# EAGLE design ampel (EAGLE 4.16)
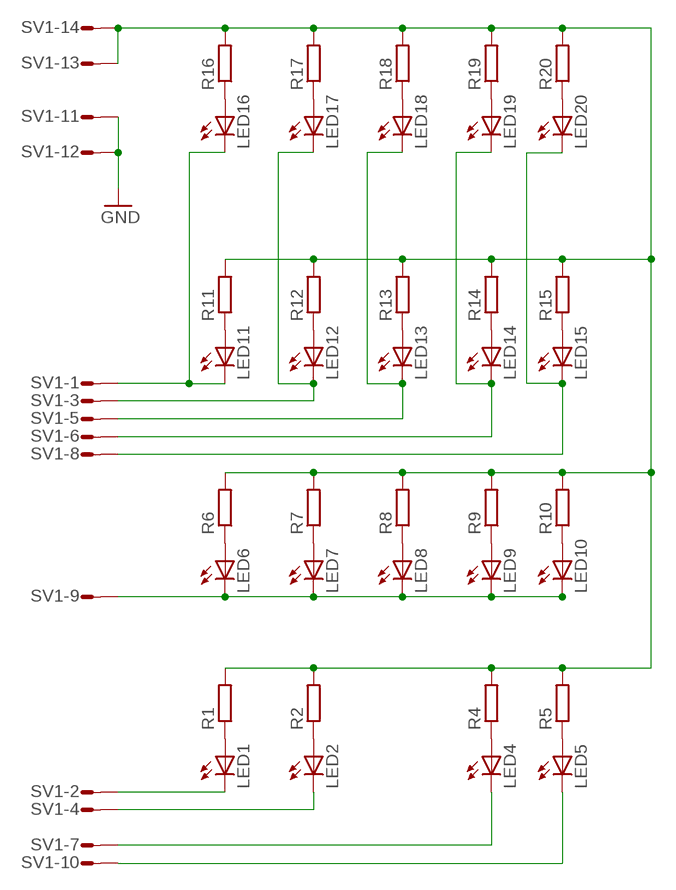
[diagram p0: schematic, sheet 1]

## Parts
LED1  LED5MM  [LED5MM]
LED2  LED5MM  [LED5MM]
LED4  LED5MM  [LED5MM]
LED5  LED5MM  [LED5MM]
LED6  LED5MM  [LED5MM]
LED7  LED5MM  [LED5MM]
LED8  LED5MM  [LED5MM]
LED9  LED5MM  [LED5MM]
LED10  LED5MM  [LED5MM]
LED11  LED5MM  [LED5MM]
LED12  LED5MM  [LED5MM]
LED13  LED5MM  [LED5MM]
LED14  LED5MM  [LED5MM]
LED15  LED5MM  [LED5MM]
LED16  LED5MM  [LED5MM]
LED17  LED5MM  [LED5MM]
LED18  LED5MM  [LED5MM]
LED19  LED5MM  [LED5MM]
LED20  LED5MM  [LED5MM]
R1  R-EU_0207/10  [0207/10]
R2  R-EU_0207/10  [0207/10]
R4  R-EU_0207/10  [0207/10]
R5  R-EU_0207/10  [0207/10]
R6  R-EU_0207/10  [0207/10]
R7  R-EU_0207/10  [0207/10]
R8  R-EU_0207/10  [0207/10]
R9  R-EU_0207/10  [0207/10]
R10  R-EU_0207/10  [0207/10]
R11  R-EU_0207/10  [0207/10]
R12  R-EU_0207/10  [0207/10]
R13  R-EU_0207/10  [0207/10]
R14  R-EU_0207/10  [0207/10]
R15  R-EU_0207/10  [0207/10]
R16  R-EU_0207/10  [0207/10]
R17  R-EU_0207/10  [0207/10]
R18  R-EU_0207/10  [0207/10]
R19  R-EU_0207/10  [0207/10]
R20  R-EU_0207/10  [0207/10]
SV1  S14P  [S14P]

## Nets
GND: SV1.11 SV1.12
N$1: LED1.A R1.1
N$2: LED2.A R2.1
N$4: LED4.A R4.1
N$5: LED5.A R5.1
N$6: LED6.A R6.1
N$7: LED7.A R7.1
N$8: LED8.A R8.1
N$9: LED9.A R9.1
N$10: LED10.A R10.1
N$11: LED11.A R11.1
N$12: LED12.A R12.1
N$13: LED13.A R13.1
N$14: LED14.A R14.1
N$15: LED15.A R15.1
N$16: LED16.A R16.1
N$17: LED17.A R17.1
N$18: LED18.A R18.1
N$19: LED19.A R19.1
N$20: LED20.A R20.1
N$21: LED11.K(C) LED16.K(C) SV1.1
N$22: LED12.K(C) LED17.K(C) SV1.3
N$23: LED13.K(C) LED18.K(C) SV1.5
N$24: LED14.K(C) LED19.K(C) SV1.6
N$25: LED15.K(C) LED20.K(C) SV1.8
N$26: R1.2 R2.2 R4.2 R5.2 R6.2 R7.2 R8.2 R9.2 R10.2 R11.2 R12.2 R13.2 R14.2 R15.2 R16.2 R17.2 R18.2 R19.2 R20.2 SV1.13 SV1.14
N$30: LED6.K(C) LED7.K(C) LED8.K(C) LED9.K(C) LED10.K(C) SV1.9
N$31: LED1.K(C) SV1.2
N$32: LED2.K(C) SV1.4
N$34: LED4.K(C) SV1.7
N$35: LED5.K(C) SV1.10

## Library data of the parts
LED1 LED2 LED4-LED20 = led:LED: LED
R1 R2 R4-R20 = rcl:R-EU_: RESISTOR, European symbol
SV1 = con-amp-mt:S14P: AMP MT CONNECTOR

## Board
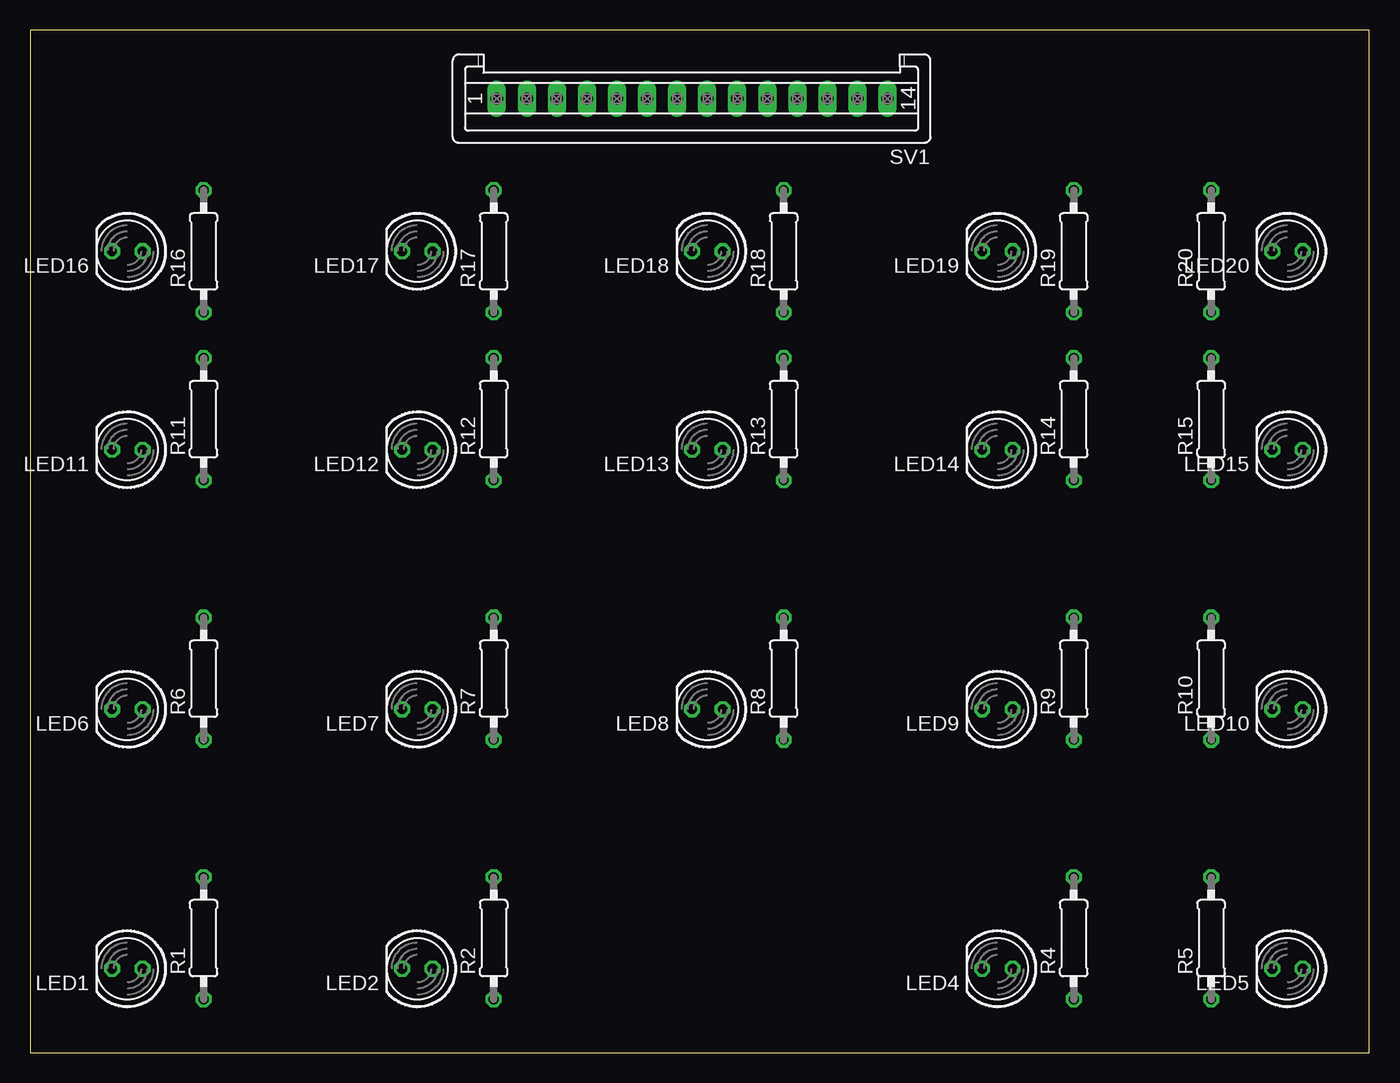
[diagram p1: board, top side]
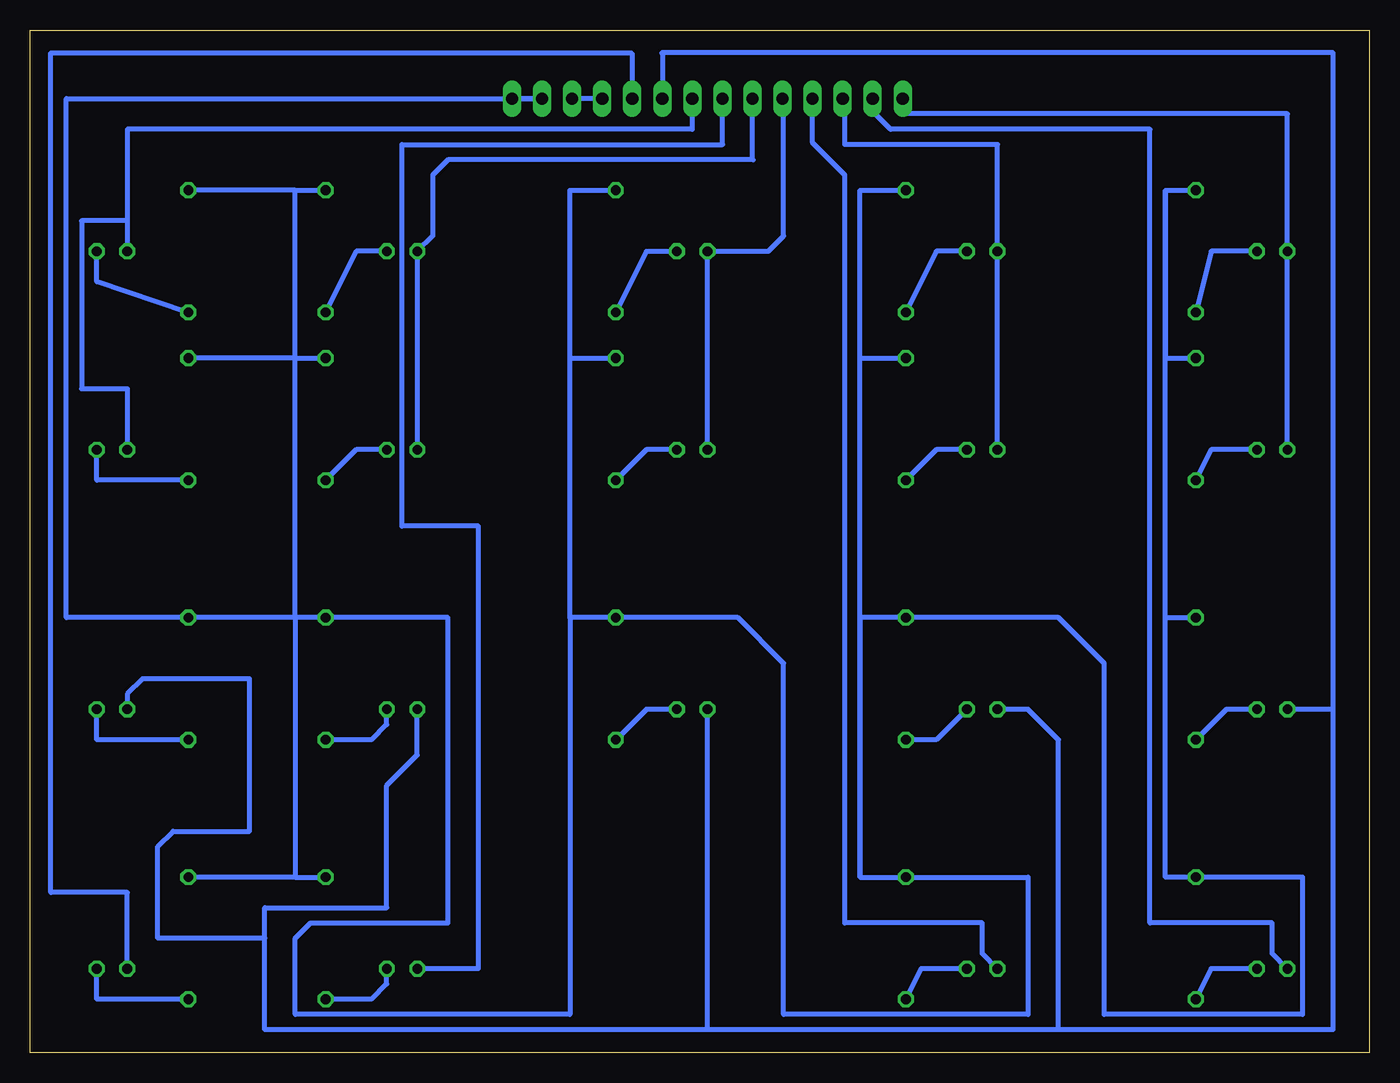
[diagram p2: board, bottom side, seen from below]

Size 111.43 x 85.08 mm. Coordinates in mm from the lower left corner, seen from the top.
Outline: 0,0 111.43,0 111.43,85.08 0,85.08 0,0
Copper layers (1*16): Top 0.035mm / dielectric 1.5mm / Bottom 0.035mm
Design rules "default": minimum track width 10mil, minimum drill 24mil, track to track 8mil, track to pad 8mil, pad to pad 8mil, via to via 8mil, smd to smd 8mil, copper to edge 40mil, drill to drill 8mil, minimum pad ring 10mil, minimum via ring 8mil, stop-mask expansion 4mil, vias tented up to drill 0mil, thermal gap 10mil

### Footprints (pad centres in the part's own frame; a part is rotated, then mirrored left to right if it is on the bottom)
LED5MM = drill 0.813 octagon: A -1.27,0; K 1.27,0
0207/10 = drill 0.813 octagon: 1 -5.08,0; 2 5.08,0
S14P = drill 1.016 long: 1 16.25,0; 2 13.75,0; 3 11.25,0; 4 8.75,0; 5 6.25,0; 6 3.75,0; 7 1.25,0; 8 -1.25,0; 9 -3.75,0; 10 -6.25,0; 11 -8.75,0; 12 -11.25,0; 13 -13.75,0; 14 -16.25,0

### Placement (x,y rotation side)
LED1  8.09,6.98 180 top
LED2  32.22,6.98 180 top
LED4  80.48,6.98 180 top
LED5  104.61,6.98 180 top
LED6  8.09,28.57 180 top
LED7  32.22,28.57 180 top
LED8  56.35,28.57 180 top
LED9  80.48,28.57 180 top
LED10  104.61,28.57 180 top
LED11  8.09,50.16 180 top
LED12  32.22,50.16 180 top
LED13  56.35,50.16 180 top
LED14  80.48,50.16 180 top
LED15  104.61,50.16 180 top
LED16  8.09,66.67 180 top
LED17  32.22,66.67 180 top
LED18  56.35,66.67 180 top
LED19  80.48,66.67 180 top
LED20  104.61,66.67 180 top
R1  14.44,9.52 90 top
R2  38.57,9.52 90 top
R4  86.83,9.52 90 top
R5  98.26,9.52 90 top
R6  14.44,31.11 90 top
R7  38.57,31.11 90 top
R8  62.7,31.11 90 top
R9  86.83,31.11 90 top
R10  98.26,31.11 90 top
R11  14.44,52.7 90 top
R12  38.57,52.7 90 top
R13  62.7,52.7 90 top
R14  86.83,52.7 90 top
R15  98.26,52.7 90 top
R16  14.44,66.67 90 top
R17  38.57,66.67 90 top
R18  62.7,66.67 90 top
R19  86.83,66.67 90 top
R20  98.26,66.67 90 top
SV1  55.08,79.37 180 top

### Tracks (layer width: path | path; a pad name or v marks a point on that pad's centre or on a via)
GND
  Bottom 0.406: 66.51,79.37 SV1.12 SV1.11
N$1
  Bottom 0.406: LED1.A 13.17,6.98 R1.1
N$2
  Bottom 0.406: LED2.A 37.3,6.98 R2.1
N$4
  Bottom 0.406: LED4.A 81.75,5.71 83.02,4.44 R4.1
N$5
  Bottom 0.406: R5.1 105.88,4.44 LED5.A
N$6
  Bottom 0.406: LED6.A 11.9,28.57 R6.1
N$7
  Bottom 0.406: R7.1 36.03,26.03 LED7.A
N$8
  Bottom 0.406: LED8.A 60.16,28.57 R8.1
N$9
  Bottom 0.406: LED9.A 81.75,27.3 83.02,26.03 R9.1
N$10
  Bottom 0.406: R10.1 105.88,26.03 LED10.A
N$11
  Bottom 0.406: LED11.A 13.17,50.16 R11.1
N$12
  Bottom 0.406: LED12.A 36.03,50.16 R12.1
N$13
  Bottom 0.406: LED13.A 60.16,50.16 R13.1
N$14
  Bottom 0.406: LED14.A 84.29,50.16 R14.1
N$15
  Bottom 0.406: R15.1 105.88,47.62 LED15.A
N$16
  Bottom 0.406: LED16.A 13.17,66.67 R16.1
N$17
  Bottom 0.406: LED17.A 36.03,66.67 R17.1
N$18
  Bottom 0.406: LED18.A 60.16,66.67 R18.1
N$19
  Bottom 0.406: LED19.A 84.29,66.67 R19.1
N$20
  Bottom 0.406: R20.1 105.88,64.13 LED20.A
N$21
  Bottom 0.406: LED11.K LED16.K 6.82,78.1 38.57,78.1 38.57,79.37 SV1.1
N$22
  Bottom 0.406: LED12.K LED17.K 30.95,75.56 43.65,75.56 43.65,79.37 SV1.3
N$23
  Bottom 0.406: LED13.K LED18.K 50,66.67 48.73,67.94 48.73,79.37 SV1.5
N$24
  Bottom 0.406: LED19.K LED14.K LED19.K | SV1.6 51.33,74.35 51.27,74.29 76.67,74.29 77.94,73.02 77.94,67.94 LED19.K
N$25
  Bottom 0.406: 103.34,69.21 LED20.K | 103.34,69.21 107.15,69.21 107.15,55.24 103.34,55.24 LED15.K | 103.34,69.21 103.34,76.83 56.35,76.83 56.35,79.37 SV1.8
N$26
  Bottom 0.406: 16.98,14.6 16.98,36.19 | 16.98,36.19 R6.2 | 16.98,36.19 16.98,57.78 | 16.98,57.78 R11.2 | 16.98,71.75 16.98,57.78 | 16.98,71.75 R16.2 | 42.38,36.19 42.38,14.6 | 42.38,36.19 R7.2 25.87,36.19 22.06,32.38 22.06,3.17 5.55,3.17 5.55,14.6 R1.2 16.98,14.6 | 42.38,36.19 42.38,57.78 | 42.38,57.78 R12.2 | 42.38,57.78 42.38,71.75 | 42.38,71.75 R17.2 | 66.51,36.19 R8.2 52.54,36.19 48.73,32.38 48.73,3.17 28.41,3.17 28.41,14.6 R2.2 42.38,14.6 | 66.51,36.19 66.51,57.78 | 66.51,57.78 63.97,57.78 | 66.51,57.78 R13.2 | 66.51,57.78 66.51,71.75 R18.2 | 89.37,14.6 R4.2 | 89.37,36.19 89.37,14.6 | 89.37,36.19 R9.2 76.67,36.19 76.67,10.79 88.1,10.79 89.37,9.52 89.37,3.17 66.51,3.17 66.51,36.19 | 89.37,36.19 89.37,57.78 | 89.37,57.78 R14.2 | 89.37,57.78 89.37,71.75 | 89.37,71.75 R19.2 | 89.37,14.6 R5.2 | 89.37,36.19 R10.2 108.42,36.19 108.42,79.37 SV1.13 SV1.14 71.59,79.37 | 89.37,57.78 R15.2 | 89.37,71.75 R20.2 | 16.98,14.6 16.98,71.75 | 42.38,14.6 42.38,71.75
N$30
  Bottom 0.406: LED10.K 103.34,29.84 102.07,31.11 93.18,31.11 93.18,18.41 99.53,18.41 100.8,17.14 100.8,9.52 91.91,9.52 | 91.91,9.52 91.91,1.9 55.08,1.9 | 55.08,1.9 LED8.K | LED9.K 79.21,24.76 81.75,22.22 81.75,12.06 91.91,12.06 91.91,9.52 | LED7.K 28.41,28.57 25.87,26.03 25.87,1.9 | 25.87,1.9 55.08,1.9 | 25.87,1.9 3.01,1.9 3.01,28.57 | 3.01,28.57 LED6.K | SV1.9 58.83,83.12 58.89,83.18 3.01,83.18 3.01,28.57
N$31
  Bottom 0.406: SV1.2 41.33,78.32 39.84,76.83 18.25,76.83 18.25,10.79 8.09,10.79 8.09,8.25 LED1.K
N$32
  Bottom 0.406: SV1.4 46.33,75.7 43.65,73.02 43.65,10.79 32.22,10.79 32.22,8.25 LED2.K
N$34
  Bottom 0.406: LED4.K 74.13,6.98 74.13,43.81 80.48,43.81 80.48,75.56 53.81,75.56 53.81,79.37 SV1.7
N$35
  Bottom 0.406: LED5.K 103.34,13.33 109.69,13.33 109.69,83.18 61.43,83.18 61.33,83.08 SV1.10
